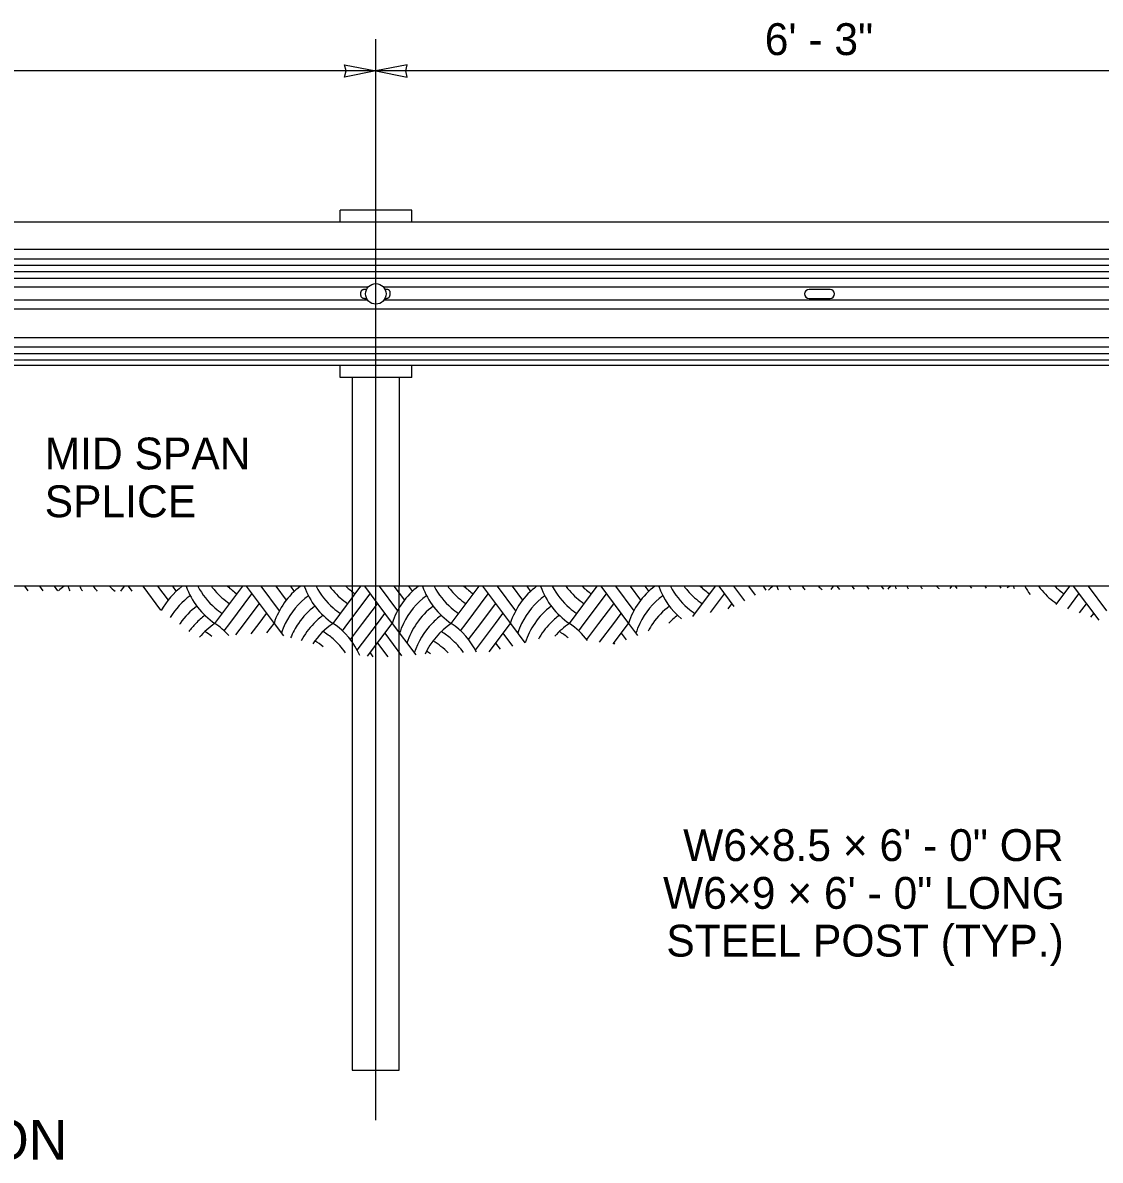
# Model space of a CAD drawing. Extents: x 99862 to 103680, y 99470 to 102076.
# Drawn here: x 101011 to 101552, y 100797 to 101369 of the extents above; entities that cross this region are included whole.
import ezdxf

# ---------------------------------------------------------------- set-up
doc = ezdxf.new("R2010")
doc.units = 0
for name, color, linetype in [('Level 14', 7, 'Continuous'), ('Level 15', 7, 'Continuous'), ('Level 2', 7, 'Continuous'), ('Level 20', 7, 'Continuous'), ('Level 27', 7, 'Continuous'), ('Level 4', 7, 'Continuous'), ('Level 7', 7, 'Continuous')]:
    doc.layers.add(name, color=color, linetype=linetype)

msp = doc.modelspace()

# ---------------------------------------------------------------- linework, layer by layer
at = {"layer": 'Level 14'}
for p, q in [((101188.31, 100817.51), (101188.31, 101360.59)), ((102045.91, 101085.68), (99896.57, 101085.68)), ((101011.74, 101085.68), (101013.39, 101083.48)), ((101019.17, 101085.68), (101020.85, 101083.44)), ((101026.59, 101085.68), (101028.3, 101083.4)), ((101060.14, 101083.22), (101061.99, 101085.68)), ((101063.71, 101085.68), (101065.58, 101083.19)), ((101071.14, 101085.68), (101080.11, 101073.71)), ((101078.56, 101085.68), (101083.82, 101078.67)), ((101085.99, 101085.68), (101087.89, 101083.13)), ((101107.4, 101067.03), (101121.38, 101085.68)), ((101123.11, 101085.68), (101137.1, 101067.03)), ((101130.53, 101085.68), (101139.77, 101073.36)), ((101137.96, 101085.68), (101143.21, 101078.67)), ((101145.38, 101085.68), (101147.29, 101083.13)), ((101166.79, 101067.03), (101180.78, 101085.68)), ((101182.5, 101085.68), (101196.49, 101067.03)), ((101189.93, 101085.68), (101199.17, 101073.36)), ((101197.35, 101085.68), (101202.61, 101078.67)), ((101204.78, 101085.68), (101206.69, 101083.13)), ((101226.19, 101067.03), (101240.18, 101085.68)), ((101241.9, 101085.68), (101255.89, 101067.03)), ((101249.32, 101085.68), (101258.56, 101073.36)), ((101256.75, 101085.68), (101262.01, 101078.67)), ((101264.17, 101085.68), (101266.08, 101083.13)), ((101285.58, 101067.03), (101299.57, 101085.68)), ((101301.3, 101085.68), (101315.28, 101067.03)), ((101308.72, 101085.68), (101317.96, 101073.36)), ((101316.15, 101085.68), (101321.4, 101078.67)), ((101323.57, 101085.68), (101325.48, 101083.13)), ((101347.63, 101070.56), (101358.97, 101085.68)), ((101360.69, 101085.68), (101368.32, 101075.51)), ((101368.12, 101085.68), (101373.63, 101078.33)), ((101375.54, 101085.68), (101378.94, 101081.15)), ((101382.97, 101085.68), (101384.39, 101083.78)), ((101417.15, 101084.06), (101418.36, 101085.68)), ((101420.09, 101085.68), (101421.27, 101084.1)), ((101427.51, 101085.68), (101428.65, 101084.16)), ((101434.94, 101085.68), (101436.03, 101084.23)), ((101442.36, 101085.68), (101443.4, 101084.29)), ((101476.93, 101084.58), (101477.76, 101085.68)), ((101479.48, 101085.68), (101480.29, 101084.61)), ((101486.91, 101085.68), (101487.67, 101084.67)), ((101494.33, 101085.68), (101495.04, 101084.73)), ((101501.76, 101085.68), (101502.42, 101084.8)), ((101530.34, 101076.59), (101537.16, 101085.68)), ((101538.88, 101085.68), (101551.65, 101068.65)), ((101546.3, 101085.68), (101555.54, 101073.36)), ((101114.82, 101067.03), (101125.96, 101081.88)), ((101174.22, 101067.03), (101185.35, 101081.88)), ((101233.61, 101067.03), (101244.75, 101081.88)), ((101293.01, 101067.03), (101304.15, 101081.88)), ((101356.49, 101072.48), (101363.54, 101081.88)), ((101536.15, 101074.43), (101541.73, 101081.88)), ((101122.25, 101067.03), (101129.67, 101076.93)), ((101181.64, 101067.03), (101189.07, 101076.93)), ((101241.04, 101067.03), (101248.46, 101076.93)), ((101300.43, 101067.03), (101307.86, 101076.93)), ((101365.35, 101074.39), (101367.25, 101076.93)), ((101541.95, 101072.27), (101545.44, 101076.93)), ((101129.67, 101067.03), (101133.38, 101071.98)), ((101189.07, 101067.03), (101192.78, 101071.98)), ((101248.46, 101067.03), (101252.18, 101071.98)), ((101307.86, 101067.03), (101311.57, 101071.98)), ((101547.75, 101070.11), (101549.16, 101071.98)), ((101112.05, 101063.34), (101114.82, 101067.03)), ((101117.89, 101061.22), (101122.25, 101067.03)), ((101125.69, 101061.72), (101129.67, 101067.03)), ((101133.49, 101062.22), (101137.1, 101067.03)), ((101137.1, 101067.03), (101141.83, 101060.72)), ((101171.45, 101063.34), (101174.22, 101067.03)), ((101175.52, 101058.87), (101181.64, 101067.03)), ((101178.97, 101053.56), (101189.07, 101067.03)), ((101184.11, 101050.52), (101196.49, 101067.03)), ((101196.49, 101067.03), (101208.33, 101051.25)), ((101230.84, 101063.34), (101233.61, 101067.03)), ((101234.92, 101058.87), (101241.04, 101067.03)), ((101238.36, 101053.56), (101248.46, 101067.03)), ((101245.19, 101052.76), (101255.89, 101067.03)), ((101255.89, 101067.03), (101263.2, 101057.28)), ((101290.24, 101063.34), (101293.01, 101067.03)), ((101294.32, 101058.87), (101300.43, 101067.03)), ((101300.79, 101057.61), (101307.86, 101067.03)), ((101307.54, 101056.71), (101315.28, 101067.03)), ((101315.28, 101067.03), (101319.82, 101060.98)), ((101189.07, 101057.13), (101194.28, 101050.19)), ((101192.78, 101062.08), (101201.25, 101050.78)), ((101248.46, 101057.13), (101250.8, 101054.02)), ((101252.18, 101062.08), (101257, 101055.65)), ((101307.86, 101057.13), (101308.25, 101056.61)), ((101311.57, 101062.08), (101314.1, 101058.71)), ((101185.35, 101052.18), (101186.79, 101050.27))]:
    msp.add_line(p, q, dxfattribs=at)
for centre, start, end in [((101054.11, 101055.64), 126.9281, 132.3867), ((101068.96, 101098.22), 199.4922, 203.2844), ((101072.67, 101103.17), 207.7361, 211.8672), ((101076.39, 101108.12), 216.664, 220.9416), ((101080.1, 101113.07), 226.7895, 232.5455), ((101113.51, 101055.64), 126.9281, 151.6752), ((101128.36, 101098.22), 199.4922, 236.0964), ((101132.07, 101103.17), 207.7361, 228.9599), ((101135.78, 101108.12), 216.664, 220.9416), ((101139.49, 101113.07), 226.7895, 236.0964), ((101172.91, 101055.64), 126.9281, 162.3566), ((101187.75, 101098.22), 199.4922, 236.0964), ((101191.47, 101103.17), 207.7361, 228.9599), ((101195.18, 101108.12), 216.664, 220.9416), ((101198.89, 101113.07), 226.7895, 236.0964), ((101232.3, 101055.64), 126.9281, 162.3566), ((101247.15, 101098.22), 199.4922, 236.0964), ((101250.86, 101103.17), 207.7361, 228.9599), ((101254.58, 101108.12), 216.664, 220.9416), ((101258.29, 101113.07), 226.7895, 236.0964), ((101291.7, 101055.64), 126.9281, 162.3566), ((101306.55, 101098.22), 199.4922, 236.0964), ((101310.26, 101103.17), 207.7361, 228.9599), ((101313.97, 101108.12), 216.664, 220.9416), ((101317.68, 101113.07), 226.7895, 236.0964), ((101351.09, 101055.64), 126.9281, 162.3566), ((101365.94, 101098.22), 199.4922, 230.243), ((101369.65, 101103.17), 207.7361, 228.9599), ((101373.37, 101108.12), 216.664, 220.9416), ((101377.08, 101113.07), 226.7895, 236.0964), ((101410.49, 101055.64), 126.9281, 131.4773), ((101425.34, 101098.22), 199.4922, 202.5012), ((101429.05, 101103.17), 207.7361, 210.8648), ((101432.76, 101108.12), 216.664, 220.0227), ((101436.47, 101113.07), 226.7895, 230.6094), ((101469.89, 101055.64), 126.9281, 130.2769), ((101484.73, 101098.22), 199.4922, 201.6648), ((101488.45, 101103.17), 207.7361, 209.9674), ((101492.16, 101108.12), 216.664, 219.0215), ((101495.87, 101113.07), 226.7895, 229.4114), ((101529.28, 101055.64), 126.9281, 129.0455), ((101544.13, 101098.22), 199.4922, 201.4245), ((101547.84, 101103.17), 207.7361, 215.178), ((101551.56, 101108.12), 216.664, 220.9416), ((101555.27, 101113.07), 226.7895, 236.0964), ((101076.39, 101108.12), 220.9415, 221.3588), ((101117.22, 101050.69), 126.3063, 149.0881), ((101135.78, 101108.12), 220.9415, 236.0964), ((101176.62, 101050.69), 126.3063, 154.2266), ((101195.18, 101108.12), 220.9415, 236.0964), ((101236.01, 101050.69), 126.3063, 154.2266), ((101254.57, 101108.12), 220.9415, 236.0964), ((101295.41, 101050.69), 126.3063, 154.2266), ((101313.97, 101108.12), 220.9415, 236.0964), ((101354.81, 101050.69), 126.3063, 154.2266), ((101373.37, 101108.12), 220.9415, 236.0964), ((101551.55, 101108.12), 220.9415, 236.0964), ((101120.93, 101045.74), 127.1006, 145.4911), ((101132.07, 101103.17), 228.9599, 236.0964), ((101180.33, 101045.74), 127.1006, 145.4911), ((101191.47, 101103.17), 228.9599, 236.0964), ((101239.73, 101045.74), 127.1006, 145.4911), ((101250.86, 101103.17), 228.9599, 236.0964), ((101299.12, 101045.74), 127.1006, 145.4911), ((101310.26, 101103.17), 228.9599, 236.0964), ((101358.52, 101045.74), 127.1006, 145.4911), ((101369.65, 101103.17), 228.9599, 236.0964), ((101124.65, 101040.79), 126.331, 135.7128), ((101184.04, 101040.79), 126.331, 135.7128), ((101243.44, 101040.79), 126.331, 135.7128), ((101302.83, 101040.79), 126.331, 135.7128), ((101362.23, 101040.79), 126.331, 135.3406), ((101120.93, 101045.74), 145.491, 146.5142), ((101124.65, 101040.79), 135.7127, 143.9481), ((101128.36, 101035.84), 123.9036, 139.8835), ((101082.72, 101030.89), 51.8845, 58.5465), ((101086.44, 101035.84), 42.0193, 56.0963), ((101176.62, 101050.69), 154.2265, 162.3566), ((101180.33, 101045.74), 145.491, 158.1237), ((101184.04, 101040.79), 135.7127, 152.2208), ((101187.75, 101035.84), 123.9036, 146.1769), ((101142.12, 101030.89), 48.9597, 58.5465), ((101145.83, 101035.84), 23.5899, 56.0963), ((101236.01, 101050.69), 154.2265, 162.3566), ((101239.73, 101045.74), 145.491, 162.3566), ((101243.44, 101040.79), 135.7127, 162.3566), ((101247.15, 101035.84), 123.9036, 155.3214), ((101201.52, 101030.89), 48.9597, 58.5465), ((101205.23, 101035.84), 26.5528, 56.0963), ((101295.41, 101050.69), 154.2265, 162.3566), ((101299.12, 101045.74), 145.491, 162.0361), ((101302.83, 101040.79), 135.7127, 150.8835), ((101306.55, 101035.84), 123.9036, 138.7698), ((101260.91, 101030.89), 50.073, 58.5465), ((101264.62, 101035.84), 36.9386, 56.0963), ((101354.81, 101050.69), 154.2265, 162.3566), ((101358.52, 101045.74), 145.491, 152.4586), ((101138.41, 101025.94), 51.462, 59.3021), ((101142.12, 101030.89), 34.7818, 48.9597), ((101197.8, 101025.94), 44.3471, 59.3021), ((101201.52, 101030.89), 34.9912, 48.9597), ((101194.09, 101020.99), 54.7938, 58.4874)]:
    msp.add_arc(centre, 37.58, start, end, dxfattribs=at)
at = {"layer": 'Level 15'}
for p, q in [((101188.31, 101344.59), (100738.31, 101344.59)), ((101638.31, 101344.59), (101188.31, 101344.59))]:
    msp.add_line(p, q, dxfattribs=at)
for points in [[(101188.31, 101344.59), (101172.58, 101341.51), (101173.31, 101344.59), (101172.58, 101347.68)], [(101188.31, 101344.59), (101204.03, 101341.51), (101203.31, 101344.59), (101204.03, 101347.68)]]:
    msp.add_lwpolyline(points, close=True, dxfattribs=at)
at = {"layer": 'Level 2'}
for p, q in [((101170.31, 101268.5), (101170.31, 101274.59)), ((101206.31, 101274.59), (101170.31, 101274.59)), ((101206.31, 101268.5), (101206.31, 101274.59)), ((101170.31, 101190.59), (101170.31, 101196.69)), ((101206.31, 101190.59), (101206.31, 101196.69)), ((101206.31, 101190.59), (101170.31, 101190.59))]:
    msp.add_line(p, q, dxfattribs=at)
at = {"layer": 'Level 27'}
for p, q in [((101833.93, 101268.68), (100988.73, 101268.68)), ((102061.41, 101254.83), (99896.57, 101254.83)), ((102058.94, 101250.08), (99899.11, 101250.08)), ((101832.38, 101246.86), (100990.28, 101246.86)), ((101835.35, 101240.4), (100987.31, 101240.4)), ((101830.96, 101243.63), (100991.7, 101243.63)), ((101184.36, 101235.95), (100742.18, 101235.95)), ((101641.06, 101235.95), (101192.17, 101235.95)), ((101184.21, 101229.41), (100742.33, 101229.41)), ((101640.9, 101229.41), (101192.32, 101229.41)), ((102045.2, 101224.96), (99913.17, 101224.96)), ((102061.41, 101210.53), (99896.57, 101210.53)), ((102058.94, 101205.78), (99899.11, 101205.78)), ((101835.23, 101202.56), (100987.43, 101202.56)), ((101832.34, 101196.69), (100990.33, 101196.69)), ((101830.72, 101199.33), (100991.94, 101199.33))]:
    msp.add_line(p, q, dxfattribs=at)
at = {"layer": 'Level 4'}
for p, q in [((101176.45, 101190.59), (101176.45, 101085.68)), ((101200.09, 101190.59), (101200.09, 101085.68)), ((101176.45, 101085.68), (101176.45, 100842.59)), ((101200.09, 100842.59), (101200.09, 101085.68)), ((101176.45, 100842.59), (101200.09, 100842.59))]:
    msp.add_line(p, q, dxfattribs=at)
for points, degree in [([(101183.63, 101234.84), (101183.24, 101234.84), (101182.84, 101234.84), (101180.59, 101234.84), (101180.59, 101232.59), (101180.59, 101230.34), (101182.84, 101230.34), (101183.24, 101230.34), (101183.63, 101230.34)], 4), ([(101193.34, 101234.84), (101192.97, 101234.84), (101192.9, 101234.84)], 2), ([(101192.9, 101230.34), (101193.28, 101230.34), (101193.34, 101230.34), (101195.59, 101230.34), (101195.59, 101232.59), (101195.59, 101234.84), (101193.34, 101234.84)], 4)]:
    msp.add_open_spline(points, degree=degree, dxfattribs=at)
at = {"layer": 'Level 7'}
for p, q in [((101416.58, 101234.84), (101406.08, 101234.84)), ((101406.08, 101230.34), (101416.58, 101230.34))]:
    msp.add_line(p, q, dxfattribs=at)
msp.add_circle((101188.27, 101232.59), 5.15, dxfattribs=at)
for centre, start, end in [((101406.08, 101232.59), 90, 270), ((101416.58, 101232.59), 270, 90)]:
    msp.add_arc(centre, 2.25, start, end, dxfattribs=at)

# ---------------------------------------------------------------- texts
at = {"layer": 'Level 20'}
for s, height, p in [('6\' - 3"', 16, (101383.78, 101352.59)), ('W6×8.5 × 6\' - 0" OR', 16, (101342.75, 100947.64)), ('W6×9 × 6\' - 0" LONG ', 16, (101332.66, 100923.64)), ('STEEL POST (TYP.)', 16, (101334.31, 100899.64)), ('ELEVATION ', 20, (100883.02, 100797.59))]:
    msp.add_text(s, height=height, dxfattribs=at).set_placement(p)
for s, p in [('MID SPAN', (101021.83, 101144.4)), ('SPLICE', (101021.83, 101120.4))]:
    msp.add_text(s, height=16, rotation=360, dxfattribs=at).set_placement(p)

doc.saveas('drawing.dxf')
